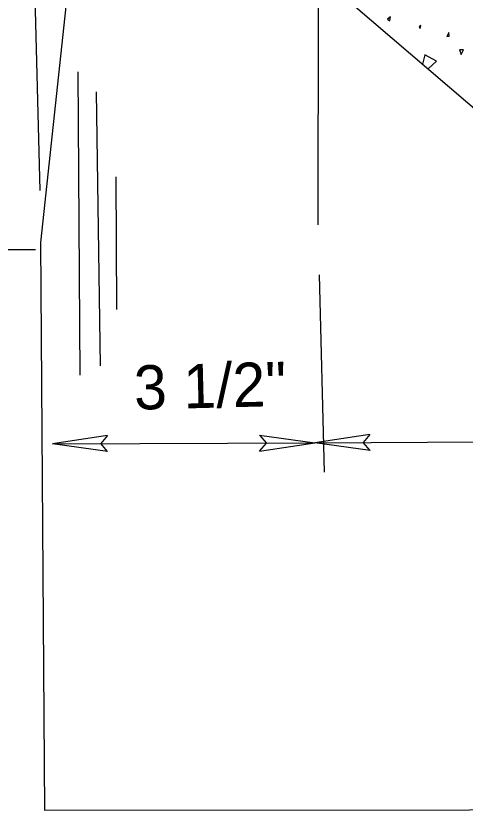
# Model space of a CAD drawing. Extents: x 1.75 to 8.12, y 0.37 to 10.28.
# Drawn here: x 3.66 to 4.27, y 3.215 to 4.294 of the extents above; entities that cross this region are included whole.
import ezdxf

# ---------------------------------------------------------------- set-up
doc = ezdxf.new("R2010")
doc.units = 0
for name, color, linetype in [('DETL-DIMS', 7, 'Continuous'), ('DETL-LINE', 7, 'Continuous'), ('DETL-NOTE', 7, 'Continuous'), ('DETL-PATT', 7, 'Continuous')]:
    doc.layers.add(name, color=color, linetype=linetype)

msp = doc.modelspace()

# ---------------------------------------------------------------- linework, layer by layer
at = {"layer": 'DETL-DIMS'}
for p, q in [((3.6931, 4.0566), (3.6859, 4.3366)), ((4.0706, 4.3104), (4.0703, 4.0102)), ((3.003, 3.9789), (3.6871, 3.9764)), ((4.072, 3.9422), (4.0789, 3.6743)), ((3.7849, 3.724), (3.7099, 3.7128)), ((3.7849, 3.724), (3.7755, 3.7131)), ((3.9908, 3.7247), (4.0659, 3.714)), ((3.9908, 3.7247), (4.0003, 3.7138)), ((4.1408, 3.7254), (4.0659, 3.714)), ((4.1408, 3.7254), (4.1315, 3.7144)), ((3.7099, 3.7128), (4.0659, 3.714)), ((3.7849, 3.7022), (3.7099, 3.7128)), ((3.7849, 3.7022), (3.7755, 3.7131)), ((3.9909, 3.7028), (4.0659, 3.714)), ((3.9909, 3.7028), (4.0003, 3.7138)), ((4.0659, 3.714), (4.4978, 3.717)), ((4.141, 3.7036), (4.0659, 3.714)), ((4.141, 3.7036), (4.1315, 3.7144))]:
    msp.add_line(p, q, dxfattribs=at)
at = {"layer": 'DETL-LINE'}
for p, q in [((3.7475, 3.8059), (3.745, 4.218)), ((3.7752, 3.8186), (3.7697, 4.1906)), ((3.7972, 3.8952), (3.7966, 4.0753))]:
    msp.add_line(p, q, dxfattribs=at)
for points in [[(3.7769, 4.7623), (3.6937, 3.9862), (3.6991, 3.2154), (5.4294, 3.2167), (5.4097, 4.8815), (3.8806, 4.8538)], [(4.5127, 3.216), (4.5105, 3.9728), (4.0653, 4.3541), (3.7401, 4.4116)]]:
    msp.add_lwpolyline(points, dxfattribs=at)
at = {"layer": 'DETL-PATT'}
for points in [[(4.1646, 4.2892), (4.1677, 4.2873), (4.1688, 4.2926)], [(4.2101, 4.2809), (4.2079, 4.2788), (4.2092, 4.2766)], [(4.2481, 4.2713), (4.2452, 4.266), (4.2482, 4.2661)], [(4.2625, 4.2475), (4.2646, 4.2413), (4.2677, 4.2476)]]:
    msp.add_lwpolyline(points, close=True, dxfattribs=at)
for points in [[(4.2197, 4.2218), (4.2313, 4.2322), (4.2154, 4.241), (4.2123, 4.2281)], [(4.2359, 4.2079), (4.236, 4.208), (4.2359, 4.2079)]]:
    msp.add_lwpolyline(points, dxfattribs=at)

# ---------------------------------------------------------------- texts
at = {"layer": 'DETL-NOTE'}
msp.add_text('3 1/2"', height=0.06, rotation=1.4676, dxfattribs=at).set_placement((3.8213, 3.759))

doc.saveas('drawing.dxf')
